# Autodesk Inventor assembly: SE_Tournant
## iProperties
Shininess: 64.0
Length Units: 11269
Angle Units: 11279
Time Units: 11290
Mass Units: 11283
Length Display Precision: 3
Angle Display Precision: 2
Compacted: True
Created: 2005-01
Part Number: SE_Tournant
Document SubType Name: Assembly
Designer: Flavien MARTY
Density: 0.0
Volumn: 0.0
Area: 0.0
PropertySet Name: Model Information
Control State: 0
Master: False
Checked Out: False
Author: Flavien MARTY
